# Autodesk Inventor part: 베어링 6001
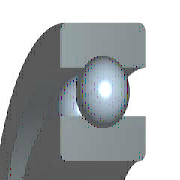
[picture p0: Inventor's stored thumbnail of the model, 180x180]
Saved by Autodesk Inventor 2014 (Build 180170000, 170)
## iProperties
Created: 2012-02
Part Number: 베어링 6001
Material: 강철, 연강
Description: 깊은 그루브 볼 베어링
Document SubType Name: Modeling
Standard: KS B 2023
Designer: mduedu
Standards Organization: KS
Language: ko-KR
Size Designation: 6001 - 12 x 28 x 8
Categories: <MemberInstance><Categories><Category DisplayName="샤프트 부품" InternalName="7f7aeb1f-a693-4053-b835-cee3144e0d98" Mnemonic="SHFT"><Category DisplayName="베어링" Inter
Density: 7.86 g/cm^3
Mass: 19.7077 g
Surface Area: 31.1809 cm^2
Volume: 2.50734 cm^3
Appearance: Yellow
IsCustomPart: 1
Author: mduedu
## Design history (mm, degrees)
sketch "스케치" dims "d0" = 4.16 (= -0.26 x WD + 0.26 x BD)
  geometry: L1 (1.92, 10)-(6.08, 10); L2 (4, 10)-(4, 7.92); L3 (4, 10)-(4, 12.08); L4 (2.454, 8.608)-(0, 8.608); L5 (0, 6)-(8, 6); L6 (2.454, 11.392)-(0, 11.392); L7 (0, 14)-(8, 14); L8 (8, 6)-(8, 8.608); L9 (5.546, 8.608)-(8, 8.608); L10 (5.546, 11.392)-(8, 11.392); L11 (8, 14)-(8, 11.392); L12 (-1.4, 0)-(8.4, 0) reference; L13 (0, -0.3)-(0, 5.3) reference
  constraints: 22 end point, 4 point on line, 2 collinear, 2 perpendicular, 2 symmetric about line, 1 midpoint, 1 parallel, 14 other
  dimensions: "d9" = 12 diameter of L5 L12 (= WD); "d11" = 28 diameter of L7 L12 (= BD); "d12" = 8 distance between parallel lines of L8 L13 (= KB); "d13" = 17.216 diameter of L9 L12 (= 0.326 x BD + 0.674 x WD)
revolve "본체" stored, may be unused: angle "d6" = 90 deg
revolve "볼" stored, may be unused: angle "d7" = 90 deg
pattern_circular "IDS_ARRAYBALL[SIMPL:T]" dims angle "d3" = 360 deg
body "Solid1"
fillet "모깎기1" dims "d1" = 0.3 (= KRS)
other parameters: "WD" = 12 [user parameter; used in 5 equation terms], "BD" = 28 [user parameter; used in 5 equation terms], "KB" = 8 [user parameter; used in 1 equation term], "KRS" = 0.3 [user parameter; used in 1 equation term], "d4" = 0, "d5" = 0, "d8" = 0, "d14" = 0, "d15" = 0, "BBA" = 0 [user parameter], "BC0" = 2360000 [user parameter], "BC" = 5070000 [user parameter], "BR" = 14 (= 0.5 x BD) [user parameter], "WR" = 6 (= 0.5 x WD) [user parameter]
